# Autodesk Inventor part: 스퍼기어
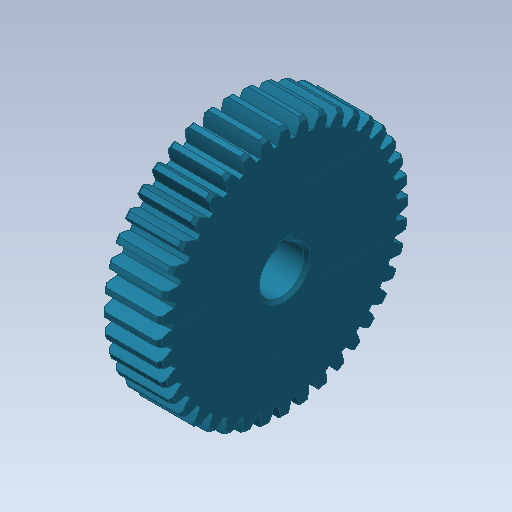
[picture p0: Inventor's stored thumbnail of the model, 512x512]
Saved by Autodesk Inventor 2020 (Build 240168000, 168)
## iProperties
CustomPartVersion: 1
Created: 2018-11
Part Number: 스퍼기어
Material: 알루미늄 6061
Document SubType Name: Modeling
Designer: mduedu
Categories: <?xml version="1.0" encoding="UTF-16"?> <MemberInstance><Categories><FamilyTemplate><FamilyTemplateParameter ValueType="xs:double" Id="1" ObjectReferenceKey="da
Density: 1 g/cm^3
Appearance: 터키옥색
Author: mduedu
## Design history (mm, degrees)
sketch "Sketch1"
  geometry: C1 r 42 at (0, 0)
  constraints: 1 centre point
  dimensions: "d0" = 83.99905 diameter of C1 (= da_da)
extrude "Extrusion1" new body sketch "Sketch1" distance "d1" = 19 (= da_b); taper "d2" = 0 deg
workplane "Work Plane2"
sketch "Sketch2"
  geometry: C1 r 42 at (0, 0) reference; C2 r 40.05 at (0, 0)
  constraints: 1 centre point, 1 coincident
  dimensions: "d3" = 80.10038 diameter of C2 (= da_dw)
feature "피치 지름" sketch "Sketch2" dims "d4" = 10, "d5" = 0
workplane "Work Plane8"
workplane "Work Plane9"
feature "스퍼 기어" dims "da_b" = 19, "da_d" = 80, "da_aw" = 80.10038, "da_da" = 83.99905, "da_df" = 75, "da_dw" = 80.10038, angle "da_beta" = 0 deg, "da_lefttooth" = 0, "da_righttooth" = 0
sketch "스케치3"
  geometry: L1 (-42, 19)-(42, 19) reference; L2 (42, 19)-(42, 0) reference; L3 (42, 0)-(-42, 0) reference; L4 (-42, 0)-(-42, 19) reference; L5 (0, 0)-(0, 19); L6 (42, 0)-(41, 0); L7 (42, 1)-(42, 0); L8 (42, 19)-(41, 19); L9 (42, 18)-(42, 19); L10 (41, 19)-(42, 18); L11 (41, 0)-(42, 1)
  constraints: 14 end point, 2 horizontal, 2 vertical, 1 midpoint
  dimensions: "d49" = 1 distance from line of L8.end L2; "d50" = 1 horizontal distance of L8.end L9.start; "d51" = 1 horizontal distance of L6.end L7.start; "d52" = 1 horizontal distance of L6.end L7.start
revolve "회전1" sketch "스케치3" stored, may be unused: angle "d53" = 90 deg
sketch "스케치4"
  geometry: L1 (-2.5, 7.071)-(2.5, 7.071); L2 (2.5, 7.071)-(2.5, 9.8); L3 (2.5, 9.8)-(-2.5, 9.8); L4 (-2.5, 9.8)-(-2.5, 7.071); A1 r 7.5 centre (0, 0) between (-2.5, 7.071) and (2.5, 7.071); 1 further point
  constraints: 8 end point, 2 parallel, 2 point on circle, 1 centre point, 1 coincident, 1 horizontal, 1 perpendicular
  dimensions: "d54" = 15 diameter of A1; "d56" = 17.3 dimension on A1 L3; "d57" = 5 distance of L2.end L3.end
extrude "돌출2" cut sketch "스케치4" extent not by distance; stored distance "d58" = 10; taper "d59" = 0 deg
chamfer "모따기1" distance "d60" = 1; stored, may be unused: second distance "d61" = 2, angle "d62" = 45 deg
sketch "스케치5"
  geometry: C1 r 17.5 at (0, 0); C2 r 28.5 at (0, 0); 1 further point
  constraints: 2 centre point, 2 coincident
  dimensions: "d63" = 35 diameter of C1; "d64" = 57 diameter of C2
extrude "돌출3" cut sketch "스케치5" distance "d65" = 9.5; taper "d66" = 0 deg
fillet "모깎기1" dims "d67" = 3
chamfer "모따기2" distance "d68" = 0.5; stored, may be unused: second distance "d69" = 2, angle "d70" = 45 deg
body "Solid1"
body "Srf1"
node "절단 모서리 투영1"
other parameters: "d16" = 80.10038 (= da_aw), "d17" = 0, "d34" = 4.5 deg (computed from da_z), "d39" = 0, "d41" = 0, "d43" = 80.10038 (= da_aw), "d46" = 80.10038 (= da_aw), "d47" = 0, "d48" = 0
